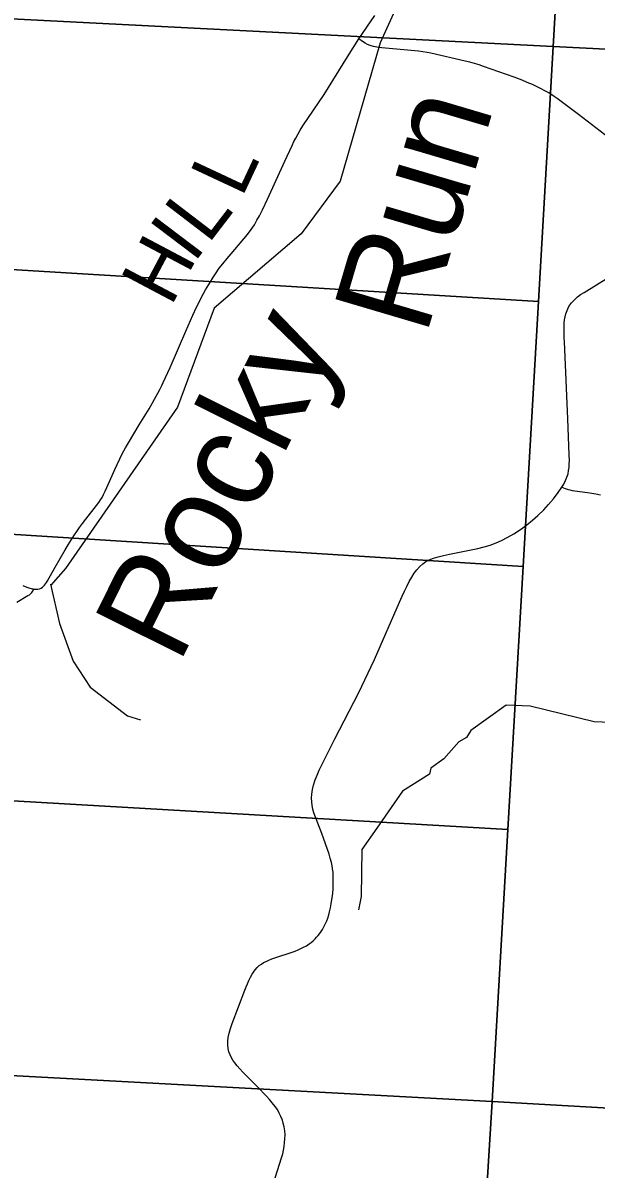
# Model space of a CAD drawing. Extents: x 396.2 to 468.4, y 232.6 to 279.1.
# Drawn here: x 422.39 to 422.946, y 275.126 to 276.238 of the extents above; entities that cross this region are included whole.
import ezdxf

# ---------------------------------------------------------------- set-up
doc = ezdxf.new("R2010")
doc.units = 0
for name, color, linetype in [('GM_X_County_Road', 7, 'Continuous'), ('GM_X_County_Road_Text', 7, 'Continuous'), ('GM_X_Minor_River', 7, 'Continuous'), ('GM_X_Minor_River_Text', 7, 'Continuous'), ('GM_X_Section', 7, 'Continuous'), ('GM_X_Township_Road', 7, 'Continuous')]:
    doc.layers.add(name, color=color, linetype=linetype)

msp = doc.modelspace()

# ---------------------------------------------------------------- linework, layer by layer
at = {"layer": 'GM_X_County_Road'}
for points in [[(422.7157, 276.2229), (422.7311, 276.2455)], [(422.3894, 275.6921), (422.3919, 275.6911), (422.3942, 275.6903), (422.3964, 275.6895), (422.3975, 275.6892), (422.3985, 275.689), (422.3994, 275.6889), (422.4003, 275.6888), (422.4023, 275.6887), (422.4041, 275.6888), (422.4057, 275.6891), (422.4073, 275.6897), (422.4085, 275.6906), (422.4095, 275.6915), (422.4105, 275.6926), (422.4114, 275.6938), (422.4124, 275.6951), (422.4134, 275.6967), (422.4209, 275.7099), (422.4306, 275.7267), (422.4335, 275.7317), (422.4367, 275.7369), (422.4395, 275.7413), (422.4419, 275.7447), (422.4446, 275.7484), (422.4473, 275.7523), (422.4506, 275.7565), (422.461, 275.7698), (422.4632, 275.7727), (422.4649, 275.7752), (422.4664, 275.7777), (422.4679, 275.7806), (422.4694, 275.7836), (422.4711, 275.7873), (422.4787, 275.8049), (422.4809, 275.8098), (422.4835, 275.8153), (422.486, 275.8201), (422.4891, 275.8258), (422.4919, 275.8307), (422.5025, 275.8482), (422.512, 275.8638), (422.5206, 275.8789), (422.5226, 275.8824), (422.5245, 275.8862), (422.5258, 275.8891), (422.5324, 275.9037), (422.5476, 275.939), (422.5546, 275.9547), (422.5582, 275.9623), (422.5602, 275.9665), (422.5624, 275.9709), (422.5645, 275.9749), (422.5669, 275.9791), (422.5715, 275.9869), (422.5738, 275.9908), (422.5764, 275.9948), (422.5802, 276.0002), (422.5835, 276.0044), (422.5878, 276.0097), (422.5917, 276.0141), (422.6075, 276.033), (422.6112, 276.0378), (422.6142, 276.0423), (422.6166, 276.0466), (422.6191, 276.051), (422.622, 276.0567), (422.627, 276.0672), (422.6439, 276.104), (422.6508, 276.1193), (422.6527, 276.1231), (422.6544, 276.1265), (422.6566, 276.1304), (422.6587, 276.1341), (422.6614, 276.1383), (422.682, 276.1688), (422.7046, 276.2052), (422.7157, 276.2229)], [(422.9584, 276.1268), (422.9287, 276.1494), (422.9082, 276.1649), (422.9043, 276.1675), (422.9, 276.1702), (422.8962, 276.1723), (422.8926, 276.1741), (422.8881, 276.1764), (422.8841, 276.1783), (422.8791, 276.1805), (422.8742, 276.1826), (422.8665, 276.1855), (422.8366, 276.196), (422.8324, 276.1975), (422.828, 276.1988), (422.8234, 276.2), (422.819, 276.2011), (422.7854, 276.2088), (422.7818, 276.2095), (422.7778, 276.2102), (422.7735, 276.2107), (422.7378, 276.2139), (422.7332, 276.2146), (422.7298, 276.2153), (422.7266, 276.2163), (422.7241, 276.2173), (422.7217, 276.2186), (422.7193, 276.2201), (422.7157, 276.2229)], [(422.7832, 275.7167), (422.784, 275.7171), (422.7881, 275.7187), (422.7925, 275.72), (422.7977, 275.7213), (422.8036, 275.7226), (422.8313, 275.7281), (422.8374, 275.7297), (422.8432, 275.7315), (422.8488, 275.7336), (422.8541, 275.736), (422.8597, 275.7389), (422.866, 275.7425), (422.8734, 275.7471), (422.8787, 275.751), (422.8843, 275.7555), (422.8895, 275.7601), (422.8951, 275.7658), (422.8997, 275.7708), (422.9045, 275.7763), (422.909, 275.7824), (422.9127, 275.7876), (422.9145, 275.7907), (422.9162, 275.794), (422.9176, 275.7974), (422.9187, 275.8007), (422.9193, 275.8038), (422.9197, 275.8067), (422.9199, 275.8101), (422.92, 275.8135), (422.9199, 275.819), (422.9185, 275.854), (422.9152, 275.9288), (422.915, 275.9327), (422.9149, 275.937), (422.9149, 275.9401), (422.9149, 275.9432), (422.9151, 275.9471), (422.9154, 275.9499), (422.9158, 275.9529), (422.9166, 275.9559), (422.9177, 275.9591), (422.9192, 275.9622), (422.9205, 275.9645), (422.9222, 275.9666), (422.9239, 275.9685), (422.9256, 275.9702), (422.9279, 275.9723), (422.9309, 275.9745), (422.9342, 275.9767), (422.9582, 275.9914)], [(422.6329, 275.1122), (422.6405, 275.1367), (422.6417, 275.1408), (422.6426, 275.1442), (422.6432, 275.1479), (422.6436, 275.1516), (422.6439, 275.1552), (422.644, 275.159), (422.6437, 275.163), (422.6431, 275.1669), (422.6423, 275.1704), (422.6414, 275.1733), (422.64, 275.1768), (422.6384, 275.1802), (422.6366, 275.1836), (422.6344, 275.1866), (422.6316, 275.1902), (422.6288, 275.1935), (422.6261, 275.1965), (422.6235, 275.1992), (422.6198, 275.2031), (422.6031, 275.2199), (422.6002, 275.2232), (422.5974, 275.2262), (422.5952, 275.229), (422.5934, 275.2315), (422.592, 275.2339), (422.5906, 275.2368), (422.5896, 275.2395), (422.5888, 275.2428), (422.5884, 275.2466), (422.5885, 275.2499), (422.5889, 275.2537), (422.5898, 275.2579), (422.591, 275.2622), (422.5928, 275.2671), (422.605, 275.2996), (422.6063, 275.3028), (422.6076, 275.3057), (422.609, 275.309), (422.6104, 275.312), (422.612, 275.3149), (422.6133, 275.317), (422.615, 275.3193), (422.6171, 275.3215), (422.619, 275.3233), (422.6211, 275.3248), (422.6232, 275.3262), (422.6256, 275.3274), (422.6282, 275.3286), (422.6313, 275.3299), (422.6537, 275.3375), (422.6567, 275.3387), (422.6593, 275.3398), (422.662, 275.3411), (422.6647, 275.3426), (422.6673, 275.3443), (422.6694, 275.3459), (422.6714, 275.3475), (422.6733, 275.3492), (422.6747, 275.3508), (422.6761, 275.3524), (422.6775, 275.3542), (422.679, 275.3563), (422.6803, 275.3584), (422.6814, 275.3604), (422.6827, 275.3629), (422.6836, 275.3648), (422.6845, 275.3669), (422.6855, 275.3694), (422.6865, 275.3725), (422.6873, 275.3756), (422.6882, 275.3793), (422.6889, 275.3834), (422.6895, 275.3875), (422.69, 275.391), (422.6903, 275.3941), (422.6906, 275.3975), (422.6907, 275.4004), (422.6908, 275.4109), (422.6906, 275.414), (422.6902, 275.4173), (422.6897, 275.4201), (422.689, 275.4234), (422.6879, 275.4277), (422.6868, 275.4316), (422.6797, 275.4515), (422.6719, 275.4717), (422.6709, 275.4752), (422.6702, 275.4787), (422.6699, 275.4822), (422.6697, 275.4858), (422.67, 275.4898), (422.6706, 275.4941), (422.6717, 275.4986), (422.6734, 275.5036), (422.6753, 275.5083), (422.6772, 275.5129), (422.6799, 275.5187), (422.6832, 275.5253), (422.6924, 275.5435), (422.7152, 275.5877), (422.7309, 275.6205), (422.7552, 275.6759), (422.7578, 275.6817), (422.76, 275.6866), (422.7621, 275.6912), (422.7646, 275.6962), (422.767, 275.7004), (422.7694, 275.7043), (422.7718, 275.7074), (422.7748, 275.7105), (422.7776, 275.7132), (422.7806, 275.7154), (422.7832, 275.7167)]]:
    msp.add_lwpolyline(points, dxfattribs=at)
at = {"layer": 'GM_X_Minor_River'}
for points in [[(422.9187, 276.7197), (422.8982, 276.6356), (422.9195, 276.5739), (422.9135, 276.5401), (422.8577, 276.4861), (422.8204, 276.4041), (422.7363, 276.2189), (422.6974, 276.0846), (422.6597, 276.0334), (422.5753, 275.9613), (422.5397, 275.8653), (422.4309, 275.7087), (422.4166, 275.6926)], [(422.4164, 275.6936), (422.4252, 275.6553), (422.4383, 275.6188), (422.4549, 275.5936), (422.4911, 275.5656), (422.5036, 275.5617)], [(422.9914, 275.5579), (422.9442, 275.5598), (422.8819, 275.5751), (422.8585, 275.5762), (422.8245, 275.5515), (422.8201, 275.5448), (422.8128, 275.5405), (422.7983, 275.5239), (422.7856, 275.5151), (422.7843, 275.5091), (422.7581, 275.4925), (422.7332, 275.4568), (422.7185, 275.436), (422.7179, 275.3905), (422.7152, 275.3773)]]:
    msp.add_lwpolyline(points, dxfattribs=at)
at = {"layer": 'GM_X_Section'}
for points in [[(422.1685, 276.3641), (422.9103, 276.3212), (422.9042, 276.2154), (422.1563, 276.2535)], [(422.9103, 276.3212), (423.5594, 276.2846), (423.5707, 276.2689), (423.5794, 276.2549), (423.6019, 276.2216), (423.6103, 276.2099), (423.6202, 276.1967), (423.6278, 276.1861), (423.6395, 276.1774), (423.1473, 276.2029), (422.9042, 276.2154)], [(421.8725, 276.2694), (422.1563, 276.2535), (422.9042, 276.2154), (422.8899, 275.9679), (421.8607, 276.0303)], [(422.9042, 276.2154), (423.1473, 276.2029), (423.1256, 275.8831), (423.1081, 275.6266), (423.0921, 275.3916), (423.0776, 275.1782), (422.8451, 275.1916), (422.8603, 275.4553), (422.875, 275.7105), (422.8899, 275.9679)], [(422.8899, 275.9679), (422.875, 275.7105), (421.8429, 275.7758), (421.8607, 276.0303)], [(421.8429, 275.7758), (422.875, 275.7105), (422.8603, 275.4553), (421.8262, 275.5154)], [(422.8603, 275.4553), (422.8451, 275.1916), (421.8083, 275.2473), (421.8262, 275.5154)], [(421.8083, 275.2473), (422.8451, 275.1916), (422.8297, 274.9443), (421.7928, 275.0058), (421.8081, 275.2441)], [(423.0776, 275.1782), (423.8389, 275.1375), (423.8717, 275.1139), (423.872, 275.1138), (423.8759, 275.057), (423.8677, 275.0293), (423.8062, 274.1333), (422.9116, 274.1851), (422.7773, 274.1944), (422.7965, 274.4451), (422.8136, 274.6978), (422.8297, 274.9443), (422.8451, 275.1916)]]:
    msp.add_lwpolyline(points, close=True, dxfattribs=at)
at = {"layer": 'GM_X_Township_Road'}
for points in [[(422.9127, 275.7876), (422.9159, 275.7863), (422.918, 275.7857), (422.9203, 275.7851), (422.9227, 275.7845), (422.9254, 275.7841), (422.9375, 275.7825), (422.9418, 275.7818), (422.9458, 275.7811), (422.9501, 275.7801)], [(422.3837, 275.6759), (422.3945, 275.6824), (422.396, 275.6833), (422.3972, 275.6843), (422.3982, 275.6853), (422.3989, 275.6864), (422.4003, 275.6888)]]:
    msp.add_lwpolyline(points, dxfattribs=at)

# ---------------------------------------------------------------- texts
at = {"layer": 'GM_X_County_Road_Text'}
for s, rotation, p in [('L', 64.9447, (422.602, 276.0676)), ('L', 52.5751, (422.5693, 276.0226)), ('I', 52.8936, (422.5553, 276.0041)), ('H', 62.0916, (422.5332, 275.9619))]:
    msp.add_text(s, height=0.0568, rotation=rotation, dxfattribs=at).set_placement(p)
at = {"layer": 'GM_X_Minor_River_Text'}
for s, rotation, p in [('Run', 73.5135, (422.7808, 275.9333)), ('Rocky', 63.5135, (422.5408, 275.6144))]:
    msp.add_text(s, height=0.0947, rotation=rotation, dxfattribs=at).set_placement(p)

doc.saveas('drawing.dxf')
